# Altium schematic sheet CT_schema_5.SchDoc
size 377 x 245 mm
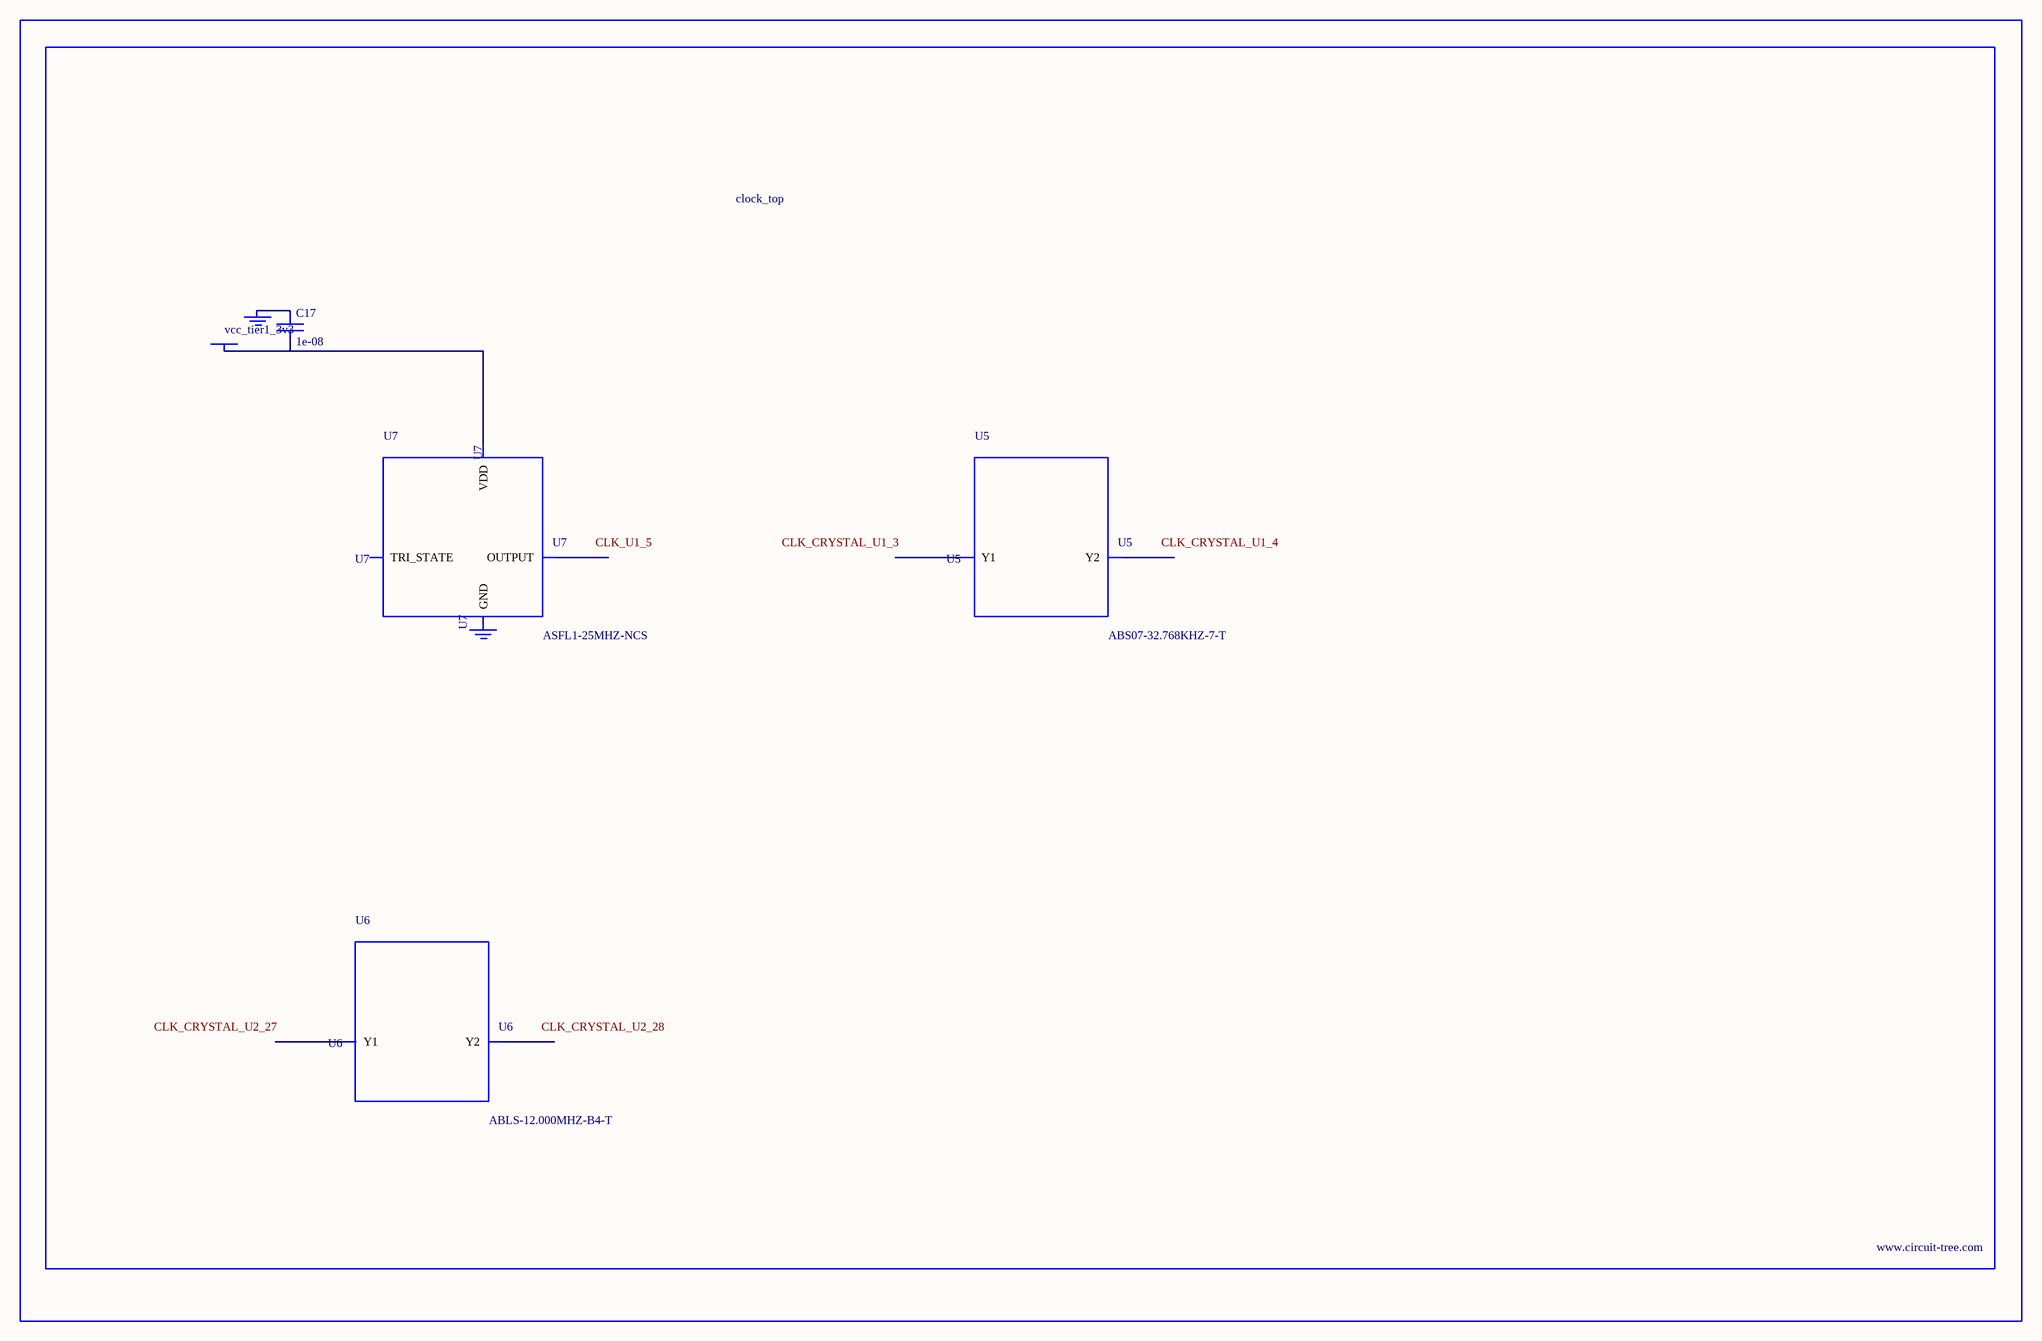
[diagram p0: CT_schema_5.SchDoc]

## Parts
BORDER4  (no value)
C17  1e-08  [C0402]
GND_INSTANCE_4_0  (no value)
GND_INSTANCE_4_1  (no value)
POWER_INSTANCE_4_0  vcc_tier1_3v3
U5  ABS07-32.768KHZ-7-T  [ABS07-32.768KHZ-7-T]
U6  ABLS-12.000MHZ-B4-T  [ABLS-12.000MHZ-B4-T]
U7  ASFL1-25MHZ-NCS  [ASFL1]

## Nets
NetC17_1: C17.1 GND_INSTANCE_4_0.0(GND)
NetC17_2: C17.2 POWER_INSTANCE_4_0.0(PWR) U7.4(VDD)

Not connected (* = marked no-connect by the designer): GND_INSTANCE_4_1 0(GND); U5 1(Y1) 2(Y2); U6 1(Y1) 2(Y2); U7 1(TRI_STATE) 2(GND) 3(OUTPUT)

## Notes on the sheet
- Labels drawn without touching a wire or pin: CLK_CRYSTAL_U1_3, CLK_CRYSTAL_U1_4, CLK_CRYSTAL_U2_27, CLK_CRYSTAL_U2_28, CLK_U1_5

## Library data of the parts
BORDER4 = BORDER_PAGE4
C17 = C0402C103K3RAC
GND_INSTANCE_4_0 GND_INSTANCE_4_1 = GND
POWER_INSTANCE_4_0 = PWR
